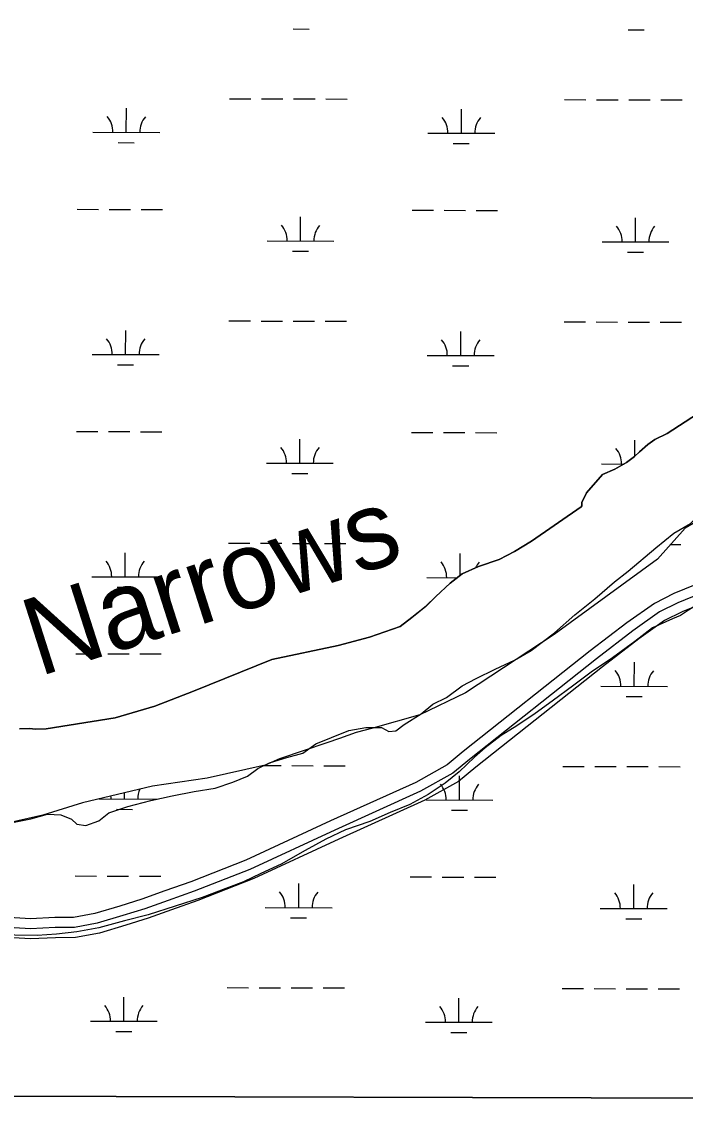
# Model space of a CAD drawing. Extents: x 3161615 to 3199515, y 867541 to 892976.
# Drawn here: x 3194939 to 3195933, y 872921 to 874536 of the extents above; entities that cross this region are included whole.
import ezdxf

# ---------------------------------------------------------------- set-up
doc = ezdxf.new("R2010")
doc.units = 0
for name, color, linetype in [('V-GRID-FRAM', 7, 'Continuous'), ('V-RIVR-IDEN', 7, 'Continuous'), ('V-ROAD-CNTR', 7, 'Continuous'), ('V-SITE-VEGE', 7, 'Continuous'), ('V-TOPO-SHOR', 7, 'Continuous'), ('V-WETL-SWMP', 7, 'Continuous')]:
    doc.layers.add(name, color=color, linetype=linetype)

msp = doc.modelspace()

# ---------------------------------------------------------------- linework, layer by layer
at = {"layer": 'V-GRID-FRAM'}
msp.add_lwpolyline([(3165877.4, 891195.5), (3197229, 891108.8), (3197186.7, 872920.9), (3165819.2, 873007.6), (3165877.4, 891195.5)], dxfattribs=at)
at = {"layer": 'V-ROAD-CNTR'}
for points in [[(3196000.9, 873714.3), (3195916, 873679.5), (3195886.9, 873665), (3195845.7, 873635.9), (3195790.8, 873593.7), (3195600.6, 873443.1), (3195576.5, 873423.4), (3195529.6, 873397), (3195401.8, 873339.2), (3195274.9, 873280.6), (3195192.2, 873248.3), (3195153.6, 873234.4), (3195119, 873222), (3195086.3, 873211.9), (3195048.7, 873200.7), (3195016.7, 873194.9), (3194988.8, 873194.5), (3194952.4, 873192.7), (3194912.5, 873195.4)], [(3196006.3, 873700.3), (3195922.2, 873665.8), (3195894.6, 873652.1), (3195854.6, 873623.9), (3195800, 873581.9), (3195610, 873431.4), (3195585, 873411), (3195536.4, 873383.6), (3195408, 873325.6), (3195280.7, 873266.7), (3195197.5, 873234.2), (3195158.7, 873220.2), (3195123.7, 873207.8), (3195090.6, 873197.6), (3195052.2, 873186.1), (3195018.1, 873179.9), (3194989.3, 873179.5), (3194952.3, 873177.6), (3194911.4, 873180.4)], [(3196006.3, 873694.9), (3195981.3, 873680.8), (3195956.6, 873666.3), (3195937.9, 873654.7), (3195925.8, 873646.6), (3195913.8, 873641.8), (3195883.9, 873628.3), (3195857.5, 873608.1), (3195824.3, 873583.2), (3195792.4, 873561.8), (3195766.4, 873542.3), (3195733.7, 873518.4), (3195708.1, 873499.9), (3195680.8, 873481.4), (3195657.2, 873467.1)], [(3196011.7, 873686.3), (3195928.4, 873652.1), (3195902.3, 873639.2), (3195863.5, 873611.8), (3195809.3, 873570.1), (3195619.4, 873419.7), (3195593.5, 873398.5), (3195543.2, 873370.2), (3195414.3, 873311.9), (3195286.6, 873252.9), (3195202.8, 873220.2), (3195163.7, 873206.1), (3195128.4, 873193.5), (3195095, 873183.2), (3195055.7, 873171.4), (3195019.6, 873165), (3194989.8, 873164.5), (3194952.1, 873162.6), (3194910.2, 873165.4)], [(3195657.2, 873467.1), (3195633.4, 873448.9), (3195617.4, 873434.8), (3195594.4, 873412.7), (3195573.5, 873395.7), (3195548.1, 873378.9), (3195520.5, 873364), (3195491, 873351.8), (3195460.4, 873338.2), (3195424.1, 873326), (3195394.7, 873312.2), (3195363.7, 873295.1), (3195327.9, 873274.7), (3195297.2, 873260.5), (3195271.3, 873248.1), (3195244.9, 873237.9)], [(3195244.9, 873237.9), (3195209.4, 873224.6), (3195168.8, 873211.5), (3195128.6, 873198.8), (3195093, 873189.5), (3195054.6, 873179.4), (3195021.9, 873173.1), (3194991.1, 873169.7), (3194962.2, 873167.7), (3194928.8, 873168.3), (3194891.8, 873170), (3194848.7, 873174.5)]]:
    msp.add_lwpolyline(points, dxfattribs=at)
at = {"layer": 'V-SITE-VEGE'}
for p, q in [((3195905.9, 873919.3), (3195997.8, 873979)), ((3195887.5, 873910.4), (3195905.9, 873919.3)), ((3195864.4, 873891.9), (3195877.2, 873902.9)), ((3195877.2, 873902.9), (3195887.5, 873910.4)), ((3195857.2, 873885), (3195864.4, 873891.9)), ((3195827.8, 873866), (3195844.9, 873875.7)), ((3195844.9, 873875.7), (3195857.2, 873885)), ((3195785.4, 873830.4), (3195809.4, 873858.1)), ((3195809.4, 873858.1), (3195827.8, 873866)), ((3195778.1, 873815.9), (3195785.4, 873830.4)), ((3195702.6, 873758), (3195777.3, 873809.3)), ((3195777.3, 873809.3), (3195778.2, 873811.1)), ((3195778.2, 873811.1), (3195778.1, 873815.9)), ((3195983.1, 873806.9), (3195933.1, 873777.5)), ((3195933.1, 873777.5), (3195891.6, 873731.3)), ((3195677.3, 873742.5), (3195702.6, 873758)), ((3195654.3, 873730.5), (3195677.3, 873742.5)), ((3195623.3, 873720.2), (3195654.3, 873730.5)), ((3195891.6, 873731.3), (3195736.8, 873618.6)), ((3195580.9, 873695.4), (3195598.7, 873709.4)), ((3195598.7, 873709.4), (3195623.3, 873720.2)), ((3195559.3, 873675.3), (3195580.9, 873695.4)), ((3195523.3, 873643.6), (3195544.7, 873660.6)), ((3195544.7, 873660.6), (3195559.3, 873675.3)), ((3195460.2, 873614.6), (3195505.9, 873630.5)), ((3195505.9, 873630.5), (3195523.3, 873643.6)), ((3195413.3, 873602), (3195460.2, 873614.6)), ((3195736.8, 873618.6), (3195604, 873530.9)), ((3195314, 873580.9), (3195413.3, 873602)), ((3195196.5, 873533.3), (3195314, 873580.9)), ((3195138.6, 873511.2), (3195196.5, 873533.3)), ((3195604, 873530.9), (3195535.3, 873498.2)), ((3195079.3, 873493.6), (3195138.6, 873511.2)), ((3194975.7, 873477.3), (3195079.3, 873493.6)), ((3195535.3, 873498.2), (3195465.1, 873478.1)), ((3194935.9, 873477.3), (3194950.5, 873477.5)), ((3194950.5, 873477.5), (3194960.2, 873476.5)), ((3194960.2, 873476.5), (3194975.7, 873477.3)), ((3195440, 873471.5), (3195415, 873462.8)), ((3195465.1, 873478.1), (3195440, 873471.5)), ((3195396, 873456.1), (3195325.3, 873432.3)), ((3195415, 873462.8), (3195396, 873456.1)), ((3195303.7, 873422.9), (3195217.1, 873403.1)), ((3195325.3, 873432.3), (3195303.7, 873422.9)), ((3195217.1, 873403.1), (3195134.9, 873391.2)), ((3195134.9, 873391.2), (3195030.3, 873366.4)), ((3195030.3, 873366.4), (3194970.7, 873347.8)), ((3194970.7, 873347.8), (3194911.1, 873334.5)), ((3194023.4, 872929.6), (3197186.7, 872920.9))]:
    msp.add_line(p, q, dxfattribs=at)
at = {"layer": 'V-TOPO-SHOR'}
for points in [[(3195847.8, 873713), (3195888.9, 873747.9), (3195916.2, 873770), (3195941.2, 873784.5), (3195951, 873794.7), (3195960.2, 873808.6), (3195977.1, 873819), (3196001.7, 873826.8), (3196031.2, 873844.1), (3196047, 873859.4), (3196076.4, 873882.3), (3196100.4, 873904.6), (3196123.9, 873924.5), (3196154, 873949.2), (3196185.9, 873973.4), (3196214.3, 873992.4), (3196251.1, 874013.5), (3196278.6, 874024.4)], [(3194935.9, 873477.3), (3194950.5, 873477.5), (3194960.2, 873476.5), (3194975.7, 873477.3), (3195079.3, 873493.6), (3195138.6, 873511.2), (3195196.5, 873533.3), (3195314, 873580.9), (3195413.3, 873602), (3195460.2, 873614.6), (3195505.9, 873630.5), (3195523.3, 873643.6), (3195544.7, 873660.6), (3195559.3, 873675.3), (3195580.9, 873695.4), (3195598.7, 873709.4), (3195623.3, 873720.2), (3195654.3, 873730.5), (3195677.3, 873742.5), (3195702.6, 873758), (3195777.3, 873809.3), (3195778.2, 873811.1), (3195778.1, 873815.9), (3195785.4, 873830.4), (3195809.4, 873858.1), (3195827.8, 873866), (3195844.9, 873875.7), (3195857.2, 873885), (3195864.4, 873891.9), (3195877.2, 873902.9), (3195887.5, 873910.4), (3195905.9, 873919.3), (3195997.8, 873979)], [(3195677.3, 873580), (3195702.5, 873594.4), (3195737.1, 873621.1), (3195767.6, 873647.8), (3195797.6, 873671.7), (3195827.3, 873697.2), (3195847.8, 873713)], [(3195454.5, 873479.1), (3195478.3, 873478.9), (3195489.3, 873473.3), (3195499.7, 873473.9), (3195512.2, 873483.5), (3195537.5, 873499.7), (3195555, 873514), (3195575.7, 873524), (3195598.8, 873541.3), (3195619.7, 873552.7), (3195648.6, 873566.6), (3195677.3, 873580)], [(3195292.6, 873417.9), (3195310.3, 873426.4), (3195336.1, 873434.3), (3195360.2, 873440.7), (3195379.7, 873454.7), (3195403.1, 873464.3), (3195429.3, 873474.4), (3195454.5, 873479.1)], [(3195069.4, 873351.3), (3195098, 873360.8), (3195132.6, 873370), (3195164.5, 873376.8), (3195197.3, 873383.2), (3195228.7, 873388.3), (3195255.3, 873397.2), (3195277.4, 873406.4), (3195292.6, 873417.9)], [(3194766.8, 873304.8), (3194793.4, 873300.7), (3194828.3, 873307.8), (3194862.4, 873320.2), (3194897, 873332.8), (3194927.8, 873337.2), (3194952.7, 873342.3), (3194977.7, 873349.4), (3194997.7, 873348.6), (3195013.7, 873341.9), (3195021.7, 873334.5), (3195034.9, 873332.6), (3195054.6, 873339.6), (3195069.4, 873351.3)]]:
    msp.add_lwpolyline(points, dxfattribs=at)
at = {"layer": 'V-WETL-SWMP'}
for p, q in [((3195345.6, 874524.8), (3195369.6, 874524.7)), ((3195847.5, 874523.4), (3195871.5, 874523.3)), ((3195250.5, 874420.4), (3195282.5, 874420.3)), ((3195298.5, 874420.3), (3195330.5, 874420.2)), ((3195346.5, 874420.2), (3195378.5, 874420.1)), ((3195394.5, 874420), (3195426.5, 874419.9)), ((3195095.8, 874370.1), (3195095.9, 874406.1)), ((3195597.7, 874368.7), (3195597.8, 874404.7)), ((3195752.4, 874419), (3195784.4, 874418.9)), ((3195800.4, 874418.9), (3195832.4, 874418.8)), ((3195848.4, 874418.8), (3195880.4, 874418.7)), ((3195896.4, 874418.6), (3195928.4, 874418.5)), ((3195045.8, 874370.2), (3195145.8, 874370)), ((3195083.7, 874354.7), (3195107.7, 874354.6)), ((3195547.7, 874368.9), (3195647.7, 874368.6)), ((3195585.6, 874353.3), (3195609.6, 874353.3)), ((3195022, 874254.9), (3195054, 874254.8)), ((3195070, 874254.7), (3195102, 874254.7)), ((3195118, 874254.6), (3195150, 874254.5)), ((3195356.7, 874207.5), (3195356.8, 874243.5)), ((3195523.9, 874253.5), (3195555.9, 874253.4)), ((3195571.9, 874253.4), (3195603.9, 874253.3)), ((3195619.9, 874253.2), (3195651.9, 874253.1)), ((3195858.7, 874206.1), (3195858.8, 874242.1)), ((3195306.7, 874207.7), (3195406.7, 874207.4)), ((3195808.7, 874206.3), (3195908.7, 874206)), ((3195344.7, 874192.1), (3195368.7, 874192.1)), ((3195846.6, 874190.7), (3195870.6, 874190.7)), ((3195249.6, 874087.7), (3195281.6, 874087.7)), ((3195297.6, 874087.6), (3195329.6, 874087.5)), ((3195345.6, 874087.5), (3195377.6, 874087.4)), ((3195393.6, 874087.3), (3195425.6, 874087.3)), ((3195751.5, 874086.4), (3195783.5, 874086.3)), ((3195799.5, 874086.2), (3195831.5, 874086.1)), ((3195847.5, 874086.1), (3195879.5, 874086)), ((3195895.5, 874086), (3195927.5, 874085.9)), ((3195094.8, 874037.4), (3195094.9, 874073.4)), ((3195596.7, 874036), (3195596.8, 874072)), ((3195044.8, 874037.6), (3195144.8, 874037.3)), ((3195546.7, 874036.2), (3195646.7, 874035.9)), ((3195082.8, 874022), (3195106.8, 874022)), ((3195584.7, 874020.6), (3195608.7, 874020.6)), ((3195997.8, 873979), (3195905.9, 873919.3)), ((3195021.1, 873922.2), (3195053.1, 873922.1)), ((3195069.1, 873922.1), (3195101.1, 873922)), ((3195117.1, 873921.9), (3195149.1, 873921.9)), ((3195523, 873920.8), (3195555, 873920.7)), ((3195571, 873920.7), (3195603, 873920.6)), ((3195619, 873920.6), (3195651, 873920.5)), ((3195905.9, 873919.3), (3195887.5, 873910.4)), ((3195355.8, 873874.8), (3195355.9, 873910.8)), ((3195857.8, 873885.5), (3195857.8, 873909.5)), ((3195877.2, 873902.9), (3195864.4, 873891.9)), ((3195887.5, 873910.4), (3195877.2, 873902.9)), ((3195864.4, 873891.9), (3195857.2, 873885)), ((3195305.8, 873875), (3195405.8, 873874.7)), ((3195807.7, 873873.6), (3195841.1, 873873.5)), ((3195844.9, 873875.7), (3195827.8, 873866)), ((3195857.2, 873885), (3195844.9, 873875.7)), ((3195343.8, 873859.5), (3195367.8, 873859.4)), ((3195809.4, 873858.1), (3195785.4, 873830.4)), ((3195827.8, 873866), (3195809.4, 873858.1)), ((3195785.4, 873830.4), (3195778.1, 873815.9)), ((3195777.3, 873809.3), (3195702.6, 873758)), ((3195778.2, 873811.1), (3195777.3, 873809.3)), ((3195778.1, 873815.9), (3195778.2, 873811.1)), ((3195983.1, 873806.9), (3195933.1, 873777.5)), ((3195933.1, 873777.5), (3195891.6, 873731.3)), ((3195702.6, 873758), (3195677.3, 873742.5)), ((3195248.7, 873755.1), (3195280.7, 873755)), ((3195296.7, 873754.9), (3195328.6, 873754.9)), ((3195344.6, 873754.8), (3195376.6, 873754.7)), ((3195392.6, 873754.7), (3195424.6, 873754.6)), ((3195677.3, 873742.5), (3195654.3, 873730.5)), ((3195911.4, 873753.2), (3195926.6, 873753.2)), ((3195093.9, 873704.8), (3195094, 873740.8)), ((3195595.8, 873707.1), (3195595.9, 873739.4)), ((3195654.3, 873730.5), (3195623.3, 873720.2)), ((3195891.6, 873731.3), (3195736.8, 873618.6)), ((3195598.7, 873709.4), (3195580.9, 873695.4)), ((3195623.3, 873720.2), (3195598.7, 873709.4)), ((3195043.9, 873704.9), (3195143.9, 873704.6)), ((3195545.8, 873703.5), (3195591.1, 873703.4)), ((3195580.9, 873695.4), (3195559.3, 873675.3)), ((3195081.9, 873689.4), (3195105.9, 873689.3)), ((3195544.8, 873660.6), (3195523.3, 873643.6)), ((3195559.3, 873675.3), (3195544.8, 873660.6)), ((3195505.9, 873630.5), (3195460.2, 873614.6)), ((3195523.3, 873643.6), (3195505.9, 873630.5)), ((3195460.2, 873614.6), (3195413.3, 873602)), ((3195736.8, 873618.6), (3195604, 873530.9)), ((3195413.3, 873602), (3195314, 873580.9)), ((3195020.2, 873589.5), (3195052.2, 873589.4)), ((3195068.2, 873589.4), (3195100.2, 873589.3)), ((3195116.2, 873589.3), (3195148.2, 873589.2)), ((3195314, 873580.9), (3195196.5, 873533.3)), ((3195856.8, 873540.8), (3195856.9, 873576.8)), ((3195196.5, 873533.3), (3195138.6, 873511.2)), ((3195604, 873530.9), (3195535.3, 873498.2)), ((3195806.8, 873540.9), (3195906.8, 873540.6)), ((3195844.8, 873525.4), (3195868.8, 873525.3)), ((3195138.6, 873511.2), (3195079.3, 873493.6)), ((3195079.3, 873493.6), (3194975.7, 873477.3)), ((3195535.3, 873498.2), (3195465.1, 873478.2)), ((3194950.5, 873477.5), (3194935.9, 873477.3)), ((3194960.2, 873476.5), (3194950.5, 873477.5)), ((3194975.7, 873477.3), (3194960.2, 873476.5)), ((3195440, 873471.5), (3195415, 873462.8)), ((3195465.1, 873478.2), (3195440, 873471.5)), ((3195396, 873456.1), (3195325.3, 873432.3)), ((3195415, 873462.8), (3195396, 873456.1)), ((3195303.7, 873422.9), (3195217.1, 873403.1)), ((3195301, 873422.3), (3195327.7, 873422.2)), ((3195325.3, 873432.3), (3195303.7, 873422.9)), ((3195343.7, 873422.1), (3195375.7, 873422)), ((3195391.7, 873422), (3195423.7, 873421.9)), ((3195749.6, 873421), (3195781.6, 873420.9)), ((3195797.6, 873420.9), (3195829.6, 873420.8)), ((3195845.6, 873420.7), (3195877.6, 873420.7)), ((3195893.6, 873420.6), (3195925.6, 873420.5)), ((3195217.1, 873403.1), (3195134.9, 873391.2)), ((3195594.9, 873370.7), (3195595, 873406.7)), ((3195134.9, 873391.2), (3195030.3, 873366.4)), ((3195054.8, 873372.2), (3195143, 873371.9)), ((3195093, 873372.1), (3195093, 873381.3)), ((3195544.9, 873370.8), (3195644.9, 873370.6)), ((3195030.3, 873366.4), (3194970.7, 873347.8)), ((3195081, 873356.7), (3195105, 873356.6)), ((3195582.9, 873355.3), (3195606.9, 873355.2)), ((3194970.7, 873347.8), (3194911.1, 873334.5)), ((3195019.3, 873256.9), (3195051.3, 873256.8)), ((3195067.3, 873256.7), (3195099.3, 873256.6)), ((3195115.3, 873256.6), (3195147.3, 873256.5)), ((3195354, 873209.5), (3195354.1, 873245.5)), ((3195521.2, 873255.5), (3195553.2, 873255.4)), ((3195569.2, 873255.3), (3195601.2, 873255.2)), ((3195617.2, 873255.2), (3195649.2, 873255.1)), ((3195855.9, 873208.1), (3195856, 873244.1)), ((3195304, 873209.6), (3195404, 873209.4)), ((3195805.9, 873208.3), (3195905.9, 873208)), ((3195341.9, 873194.1), (3195365.9, 873194)), ((3195843.9, 873192.7), (3195867.9, 873192.7)), ((3195246.8, 873089.7), (3195278.8, 873089.6)), ((3195294.8, 873089.6), (3195326.8, 873089.5)), ((3195342.8, 873089.5), (3195374.8, 873089.4)), ((3195390.8, 873089.3), (3195422.8, 873089.2)), ((3195748.7, 873088.3), (3195780.7, 873088.3)), ((3195796.7, 873088.2), (3195828.7, 873088.1)), ((3195844.7, 873088.1), (3195876.7, 873088)), ((3195892.7, 873087.9), (3195924.7, 873087.9)), ((3195092.1, 873039.4), (3195092.2, 873075.4)), ((3195594, 873038), (3195594.1, 873074)), ((3195042.1, 873039.5), (3195142.1, 873039.3)), ((3195544, 873038.2), (3195644, 873037.9)), ((3195080, 873024), (3195104, 873023.9)), ((3195581.9, 873022.6), (3195605.9, 873022.6)), ((3194023.4, 872929.6), (3197186.7, 872920.9))]:
    msp.add_line(p, q, dxfattribs=at)
for centre, start, end in [((3195040.5, 874370.7), 359.0699, 40.6135), ((3195151, 874370.4), 139.0699, 180.6135), ((3195542.4, 874369.3), 359.0699, 40.6135), ((3195652.9, 874369), 139.0699, 180.6135), ((3195301.5, 874208.2), 359.0699, 40.6135), ((3195412, 874207.8), 139.0699, 180.6135), ((3195803.4, 874206.8), 359.0699, 40.6135), ((3195913.9, 874206.5), 139.0699, 180.6135), ((3195039.6, 874038.1), 359.0699, 40.6135), ((3195150.1, 874037.8), 139.0699, 180.6135), ((3195541.5, 874036.7), 359.0699, 40.6135), ((3195652, 874036.4), 139.0699, 180.6135), ((3195300.6, 873875.5), 359.0699, 40.6135), ((3195411.1, 873875.2), 139.0699, 180.6135), ((3195802.5, 873874.1), 359.0699, 40.6135), ((3195038.7, 873705.4), 359.0699, 40.6135), ((3195149.2, 873705.1), 139.0699, 180.6135), ((3195540.6, 873704), 359.0699, 40.6135), ((3195651.1, 873703.7), 139.0699, 155.4521), ((3195801.6, 873541.4), 359.0699, 40.6135), ((3195912.1, 873541.1), 139.0699, 180.6135), ((3195148.2, 873372.4), 155.9623, 180.6135), ((3195539.7, 873371.3), 359.0699, 40.6135), ((3195650.1, 873371), 139.0699, 180.6135), ((3195037.8, 873372.7), 359.0699, 6.136), ((3195298.7, 873210.1), 359.0699, 40.6135), ((3195409.2, 873209.8), 139.0699, 180.6135), ((3195800.7, 873208.7), 359.0699, 40.6135), ((3195911.1, 873208.4), 139.0699, 180.6135), ((3195036.8, 873040), 359.0699, 40.6135), ((3195147.3, 873039.7), 139.0699, 180.6135), ((3195538.7, 873038.7), 359.0699, 40.6135), ((3195649.2, 873038.3), 139.0699, 180.6135)]:
    msp.add_arc(centre, 35.2, start, end, dxfattribs=at)

# ---------------------------------------------------------------- texts
at = {"layer": 'V-RIVR-IDEN'}
msp.add_text('Narrows', height=116, rotation=17.7447, dxfattribs=at).set_placement((3194965, 873555.1))

doc.saveas('drawing.dxf')
